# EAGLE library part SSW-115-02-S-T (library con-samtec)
THROUGH-HOLE .025" SQ POST SOCKET Source: Samtec SSW.pdf
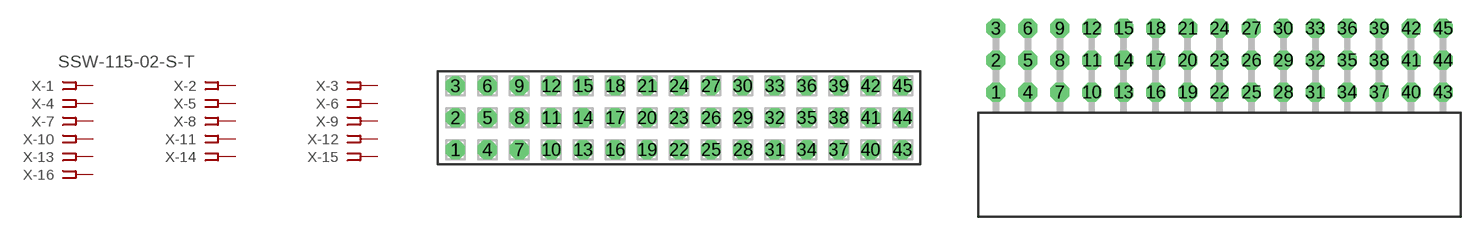
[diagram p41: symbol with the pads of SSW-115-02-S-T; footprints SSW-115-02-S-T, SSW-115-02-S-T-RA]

Designator prefix X; gates -1=FPINV -2=FPIN -3=FPIN -4=FPIN -5=FPIN -6=FPIN -7=FPIN -8=FPIN -9=FPIN -10=FPIN -11=FPIN -12=FPIN -13=FPIN -14=FPIN -15=FPIN -16=FPIN -17=FPIN -18=FPIN -19=FPIN -20=FPIN -21=FPIN -22=FPIN -23=FPIN -24=FPIN -25=FPIN -26=FPIN -27=FPIN -28=FPIN -29=FPIN -30=FPIN -31=FPIN -32=FPIN -33=FPIN -34=FPIN -35=FPIN -36=FPIN -37=FPIN -38=FPIN -39=FPIN -40=FPIN -41=FPIN -42=FPIN -43=FPIN -44=FPIN -45=FPIN

## SSW-115-02-S-T (MPN: SSW-115-02-S-T; OC_FARNELL: unknown; OC_NEWARK: 82P6867)  [SSW-115-02-S-T]
1  -1:1  pas
2  -2:1  pas
3  -3:1  pas
4  -4:1  pas
5  -5:1  pas
6  -6:1  pas
7  -7:1  pas
8  -8:1  pas
9  -9:1  pas
10  -10:1  pas
11  -11:1  pas
12  -12:1  pas
13  -13:1  pas
14  -14:1  pas
15  -15:1  pas
16  -16:1  pas
17  -17:1  pas
18  -18:1  pas
19  -19:1  pas
20  -20:1  pas
21  -21:1  pas
22  -22:1  pas
23  -23:1  pas
24  -24:1  pas
25  -25:1  pas
26  -26:1  pas
27  -27:1  pas
28  -28:1  pas
29  -29:1  pas
30  -30:1  pas
31  -31:1  pas
32  -32:1  pas
33  -33:1  pas
34  -34:1  pas
35  -35:1  pas
36  -36:1  pas
37  -37:1  pas
38  -38:1  pas
39  -39:1  pas
40  -40:1  pas
41  -41:1  pas
42  -42:1  pas
43  -43:1  pas
44  -44:1  pas
45  -45:1  pas

## SSW-115-02-S-TRA (MPN: SSW-115-02-S-T-RA; OC_FARNELL: unknown; OC_NEWARK: 82P6868)  [SSW-115-02-S-T-RA]
Pads as for SSW-115-02-S-T

## Footprint SSW-115-02-S-T (pad centres in mm)
THROUGH-HOLE .025" SQ POST SOCKET Source: Samtec SSW.pdf
drill 1 pad 1.5 octagon: 1 -17.78,-2.54; 2 -17.78,0; 3 -17.78,2.54; 4 -15.24,-2.54; 5 -15.24,0; 6 -15.24,2.54; 7 -12.7,-2.54; 8 -12.7,0; 9 -12.7,2.54; 10 -10.16,-2.54; 11 -10.16,0; 12 -10.16,2.54; 13 -7.62,-2.54; 14 -7.62,0; 15 -7.62,2.54; 16 -5.08,-2.54; 17 -5.08,0; 18 -5.08,2.54; 19 -2.54,-2.54; 20 -2.54,0; 21 -2.54,2.54; 22 0,-2.54; 23 0,0; 24 0,2.54; 25 2.54,-2.54; 26 2.54,0; 27 2.54,2.54; 28 5.08,-2.54; 29 5.08,0; 30 5.08,2.54; 31 7.62,-2.54; 32 7.62,0; 33 7.62,2.54; 34 10.16,-2.54; 35 10.16,0; 36 10.16,2.54; 37 12.7,-2.54; 38 12.7,0; 39 12.7,2.54; 40 15.24,-2.54; 41 15.24,0; 42 15.24,2.54; 43 17.78,-2.54; 44 17.78,0; 45 17.78,2.54

## Footprint SSW-115-02-S-T-RA (pad centres in mm)
THROUGH-HOLE .025" SQ POST SOCKET Source: Samtec SSW.pdf
drill 1 pad 1.5 octagon: 1 -17.78,1.524; 2 -17.78,4.064; 3 -17.78,6.604; 4 -15.24,1.524; 5 -15.24,4.064; 6 -15.24,6.604; 7 -12.7,1.524; 8 -12.7,4.064; 9 -12.7,6.604; 10 -10.16,1.524; 11 -10.16,4.064; 12 -10.16,6.604; 13 -7.62,1.524; 14 -7.62,4.064; 15 -7.62,6.604; 16 -5.08,1.524; 17 -5.08,4.064; 18 -5.08,6.604; 19 -2.54,1.524; 20 -2.54,4.064; 21 -2.54,6.604; 22 0,1.524; 23 0,4.064; 24 0,6.604; 25 2.54,1.524; 26 2.54,4.064; 27 2.54,6.604; 28 5.08,1.524; 29 5.08,4.064; 30 5.08,6.604; 31 7.62,1.524; 32 7.62,4.064; 33 7.62,6.604; 34 10.16,1.524; 35 10.16,4.064; 36 10.16,6.604; 37 12.7,1.524; 38 12.7,4.064; 39 12.7,6.604; 40 15.24,1.524; 41 15.24,4.064; 42 15.24,6.604; 43 17.78,1.524; 44 17.78,4.064; 45 17.78,6.604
